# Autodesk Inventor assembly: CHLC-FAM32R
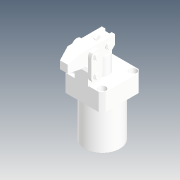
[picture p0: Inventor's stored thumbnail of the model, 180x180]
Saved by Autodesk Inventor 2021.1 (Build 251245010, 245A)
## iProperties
Created: 2019-04
Part Number: CHLC-FAM32R
Description: STEP AP214
Document SubType Name: Assembly
Designer: user
Title: CHLC-FAM32R.STEP
Revision Number: ÈÎºÎ
Sending System: SolidWorks 2016
Preprocessor: SwSTEP 2.0
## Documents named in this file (10)
- D:\Vault_2016\Projekty\Clamptek\Hydraulic\CHLC\CHLC-32\Inventor\CHLC-FAM32R\CHLC-FAM32R.iam
- D:\Vault_2016\Projekty\Clamptek\Hydraulic\CHLC\CHLC-32\Inventor\CHLC-FAM32R\CHLC-FAM32-05_1.ipt
- D:\Vault_2016\Projekty\Clamptek\Hydraulic\CHLC\CHLC-32\Inventor\CHLC-FAM32R\CHLC-32-02_1.ipt
- D:\Vault_2016\Projekty\Clamptek\Hydraulic\CHLC\CHLC-32\Inventor\CHLC-FAM32R\CHLC-32-03_1.ipt
- D:\Vault_2016\Projekty\Clamptek\Hydraulic\CHLC\CHLC-32\Inventor\CHLC-FAM32R\CHLC-32-04_1_1.ipt
- D:\Vault_2016\Projekty\Clamptek\Hydraulic\CHLC\CHLC-32\Inventor\CHLC-FAM32R\CHLC-32-08_1.ipt
- D:\Vault_2016\Projekty\Clamptek\Hydraulic\CHLC\CHLC-32\Inventor\CHLC-FAM32R\LHC01D-32-01_1.ipt
- D:\Vault_2016\Projekty\Clamptek\Hydraulic\CHLC\CHLC-32\Inventor\CHLC-FAM32R\YAKUAI.ipt
- D:\Vault_2016\Projekty\Clamptek\Hydraulic\CHLC\CHLC-32\Inventor\CHLC-FAM32R\socket set screw flat point_iso_ISO 4026 - M5 x 6-N.ipt
- D:\Vault_2016\Projekty\Clamptek\Hydraulic\CHLC\CHLC-32\Inventor\CHLC-FAM32R\Ñ¹±Û.ipt
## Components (17 placed, 17 different names)
1. CHLC-FAM32-05_1_1
2. CHLC-32-02_1_2
3. CHLC-32-03_1_3
4. CHLC-32-04_1_1_4
5. CHLC-32-08_1_5
6. LHC01D-32-01_1_6
7. YAKUAI_7
8. socket set screw flat point_iso_ISO 4026 - M5 x 6-N_8
9. socket set screw flat point_iso_ISO 4026 - M5 x 6-N_9
10. CHLC-32-03_1_10
11. LHC01D-32-01_1_11
12. LHC01D-32-01_1_12
13. LHC01D-32-01_1_13
14. LHC01D-32-01_1_14
15. LHC01D-32-01_1_15
16. CHLC-32-04_1_1_16
17. Ñ¹±Û_17
